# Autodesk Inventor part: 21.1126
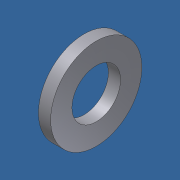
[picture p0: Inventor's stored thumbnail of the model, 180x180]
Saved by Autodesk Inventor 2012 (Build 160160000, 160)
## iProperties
Created: 2006-02
Part Number: 21.1126
Material: Steel, Mild
Description: M6 ROUND WASHER DIN 125-1A
Document SubType Name: Modeling
Standard: DIN 125
Designer: Andy Moles
Standards Organization: DIN
Language: en-US
Size Designation: A 6.4
Categories: <MemberInstance><Categories><Category DisplayName="Fasteners" InternalName="e4da775c-781d-43d5-af7c-5136215cf5a6" Mnemonic="FSTN"><Category DisplayName="Washers
Density: 7.86 g/cm^3
Vendor: S
Mass: 1.01774 g
Surface Area: 2.54343 cm^2
Volume: 0.129484 cm^3
Author: Andy Moles
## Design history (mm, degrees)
body "Solid1"
sketch "Sketch"
  geometry: C1 r 6 at (0, 0); C2 r 3.2 at (0, 0); 1 further point
  constraints: 2 centre point, 2 coincident
  dimensions: "d0" = 6.4 diameter of C2 (= SD1); "d1" = 12 diameter of C1 (= SD2)
extrude "Body" new body sketch "Sketch" distance "d2" = 1.6 (= SD); taper "d3" = 0 deg
workaxis "Work Axis1"
workplane "Work Plane1"
other parameters: "SD1" = 6.4 [user parameter; used in 1 equation term], "SD2" = 12 [user parameter; used in 1 equation term], "SD" = 1.6 [user parameter; used in 1 equation term], "d4" = 0, "d5" = 0, "d6" = 0, "d7" = 0, "NND" = 6 [user parameter]
